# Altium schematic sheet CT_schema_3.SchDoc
size 461 x 297 mm
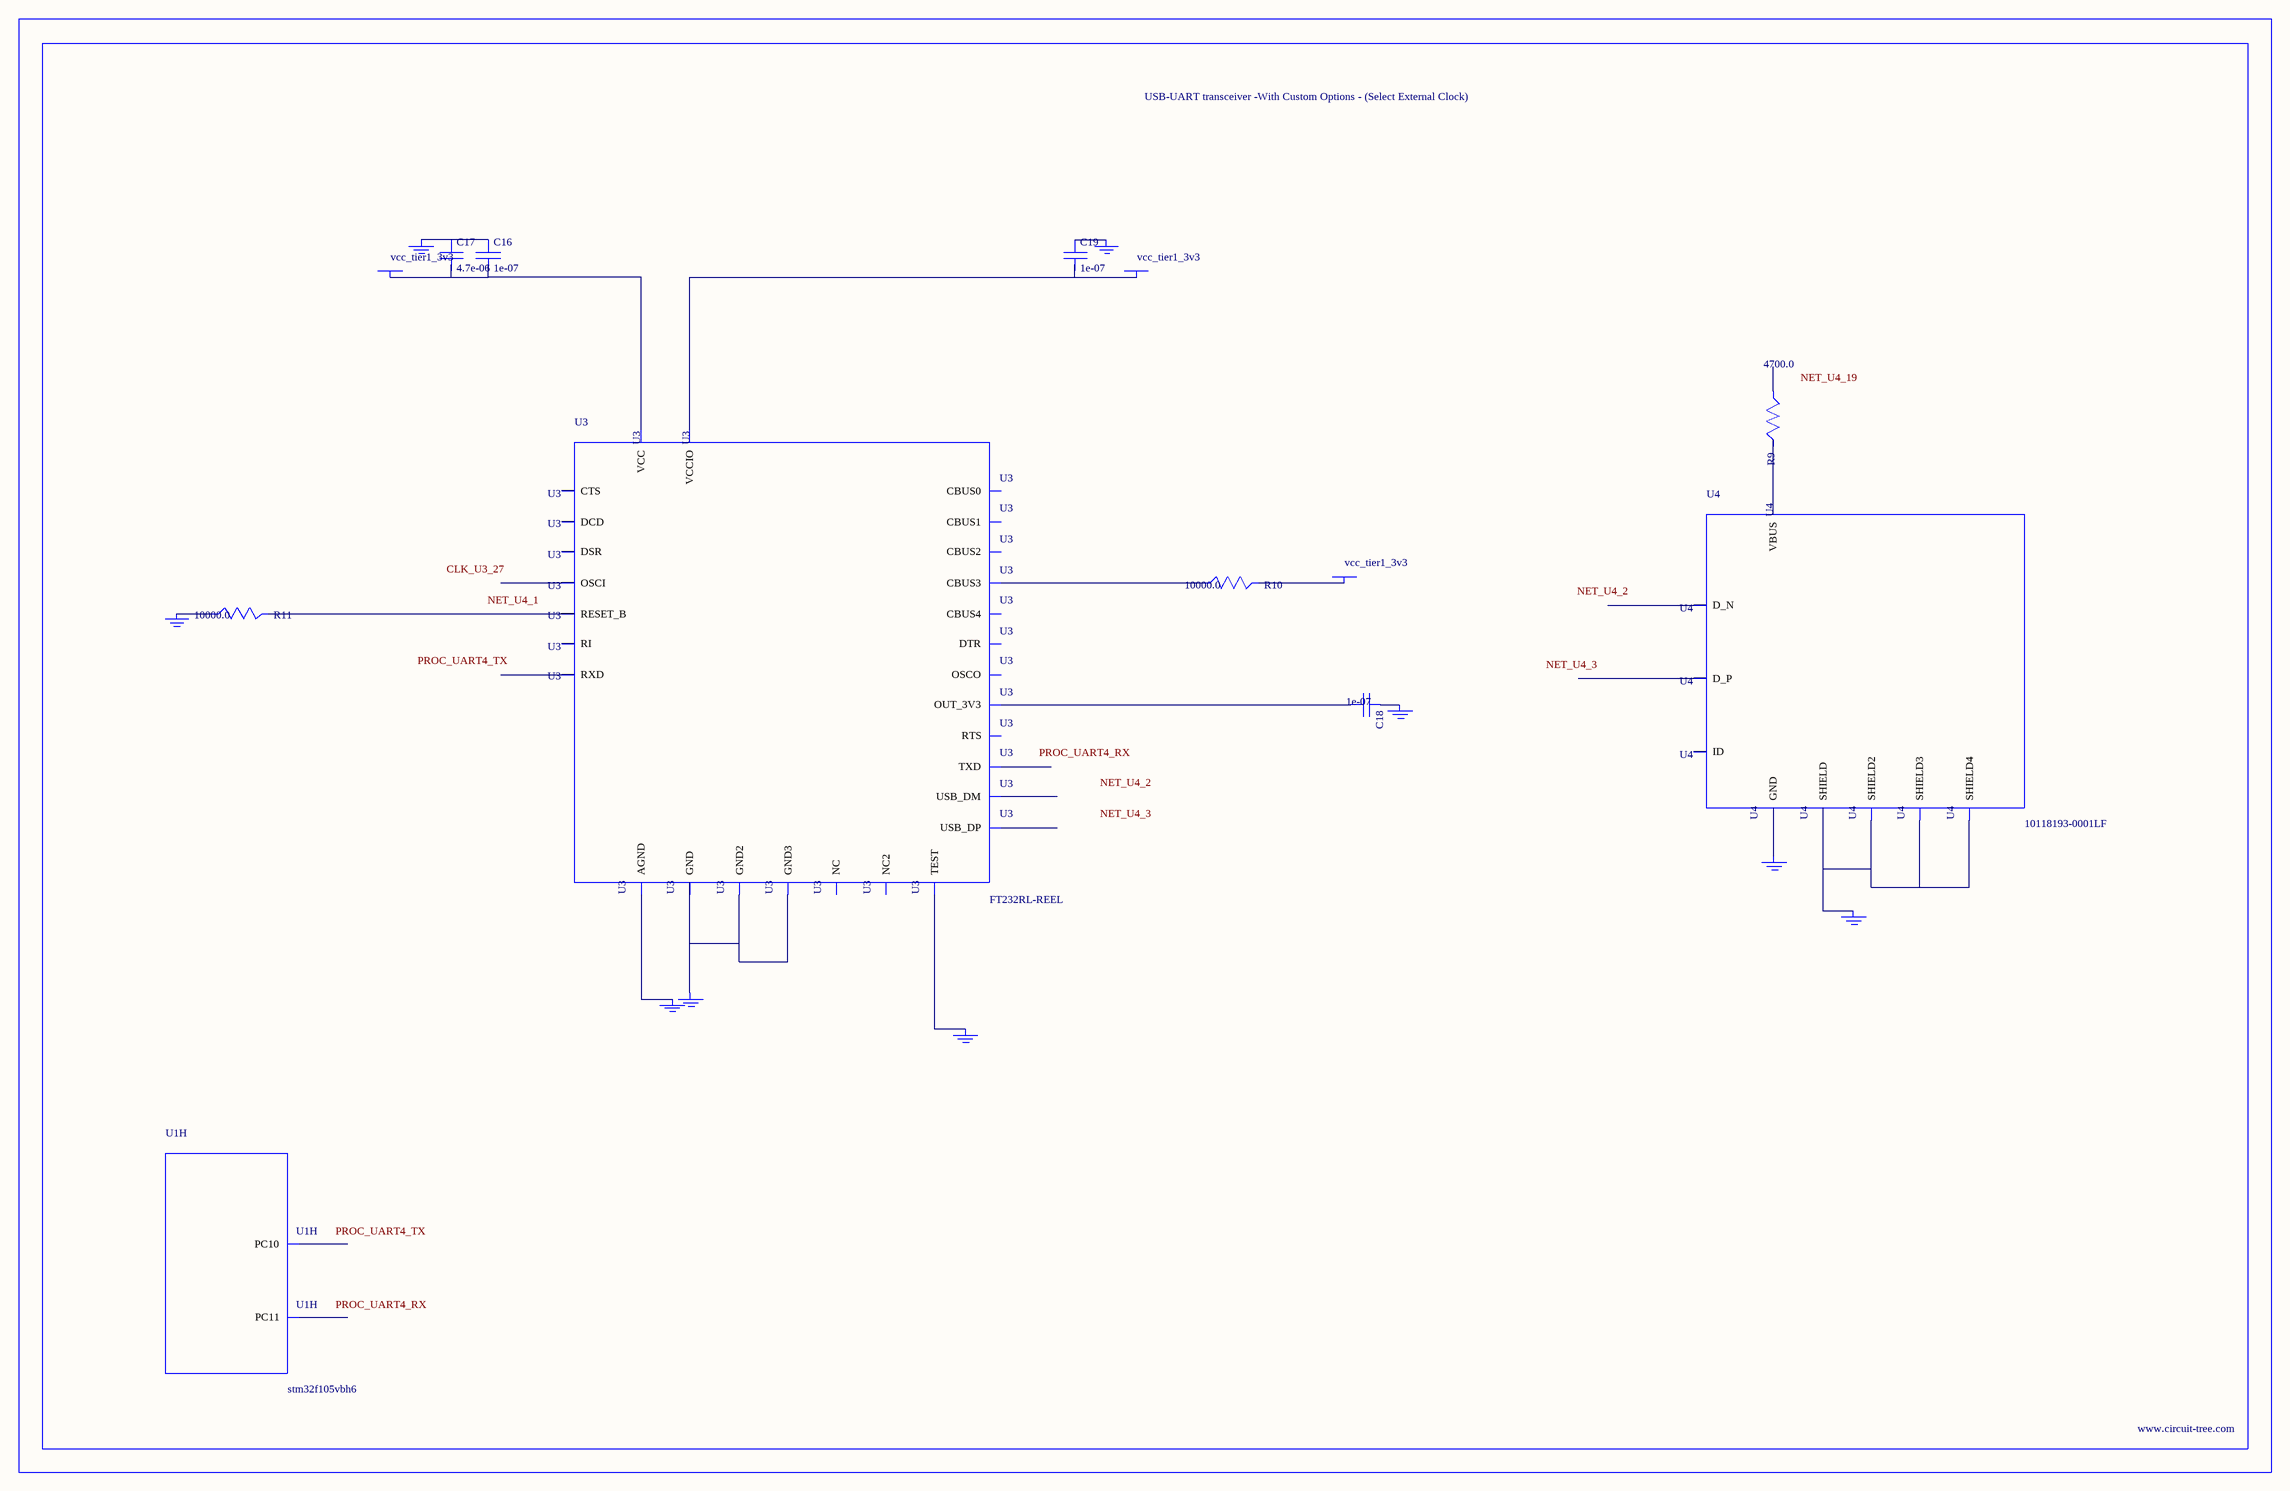
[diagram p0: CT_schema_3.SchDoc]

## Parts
BORDER2  (no value)
C16  1e-07  [C0402]
C17  4.7e-06  [C0805]
C18  1e-07  [C0402]
C19  1e-07  [C0402]
GND_INSTANCE_2_0  (no value)
GND_INSTANCE_2_1  (no value)
GND_INSTANCE_2_2  (no value)
GND_INSTANCE_2_3  (no value)
GND_INSTANCE_2_4  (no value)
GND_INSTANCE_2_5  (no value)
GND_INSTANCE_2_6  (no value)
GND_INSTANCE_2_7  (no value)
GND_INSTANCE_2_8  (no value)
POWER_INSTANCE_2_0  vcc_tier1_3v3
POWER_INSTANCE_2_1  vcc_tier1_3v3
POWER_INSTANCE_2_2  vcc_tier1_3v3
R9  4700.0  [R0603]
R10  10000.0  [R0603]
R11  10000.0  [R0603]
U1  stm32f105vbh6  [LFBGA100]  (part H of 11)
U3  FT232RL-REEL  [SSOP-28]
U4  10118193-0001LF  [FCI_10118193-0001LF]

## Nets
NetC16_1: C16.1 C17.1 GND_INSTANCE_2_3.0(GND)
NetC16_2: C16.2 C17.2 POWER_INSTANCE_2_2.0(PWR) U3.20(VCC)
NetC18_1: C18.1 GND_INSTANCE_2_1.0(GND)
NetC18_2: C18.2 U3.17(OUT_3V3)
NetC19_1: C19.1 GND_INSTANCE_2_0.0(GND)
NetC19_2: C19.2 POWER_INSTANCE_2_0.0(PWR) U3.4(VCCIO)
NetGND_INSTANCE_2_2_0: GND_INSTANCE_2_2.0(GND) R11.1
NetGND_INSTANCE_2_4_0: GND_INSTANCE_2_4.0(GND) U3.25(AGND)
NetGND_INSTANCE_2_5_0: GND_INSTANCE_2_5.0(GND) U3.26(TEST)
NetGND_INSTANCE_2_6_0: GND_INSTANCE_2_6.0(GND) U3.7(GND) U3.18(GND2) U3.21(GND3)
NetGND_INSTANCE_2_7_0: GND_INSTANCE_2_7.0(GND) U4.6(SHIELD) U4.7(SHIELD2) U4.8(SHIELD3) U4.9(SHIELD4)
NetGND_INSTANCE_2_8_0: GND_INSTANCE_2_8.0(GND) U4.5(GND)
NetPOWER_INSTANCE_2_1_0: POWER_INSTANCE_2_1.0(PWR) R10.2
NetR9_2: R9.2 U4.1(VBUS)
NetR10_1: R10.1 U3.14(CBUS3)
NetR11_2: R11.2 U3.19(RESET_B)

Not connected (* = marked no-connect by the designer): R9 1; U1 B8(PC11) B9(PC10); U3 1(TXD) 2(DTR) 3(RTS) 5(RXD) 6(RI) 8(NC) 9(DSR) 10(DCD) 11(CTS) 12(CBUS4) 13(CBUS2) 15(USB_DP) 16(USB_DM) 22(CBUS1) 23(CBUS0) 24(NC2) 27(OSCI) 28(OSCO); U4 2(D_N) 3(D_P) 4(ID)

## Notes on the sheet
- Labels drawn without touching a wire or pin: CLK_U3_27, NET_U4_1, NET_U4_2, NET_U4_3, NET_U4_19, PROC_UART4_RX, PROC_UART4_TX

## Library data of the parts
BORDER2 = BORDER_PAGE2
C16 C18 C19 = C0402C104K3RACTU
C17 = C0805C475K4RACTU
GND_INSTANCE_2_0-GND_INSTANCE_2_8 = GND
POWER_INSTANCE_2_0-POWER_INSTANCE_2_2 = PWR
R9 = RC0603JR-074K7L
R10 R11 = RC0603JR-0710KL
